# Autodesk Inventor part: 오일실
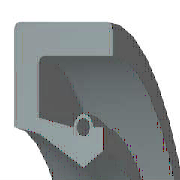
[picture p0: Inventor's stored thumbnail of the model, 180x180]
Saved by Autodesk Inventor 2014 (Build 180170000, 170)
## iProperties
IsCustomPart: 0
Created: 2009-02
Part Number: 오일실
Material: 고무
Description: 오일-실
Document SubType Name: Modeling
Standard: KS B 2804
Designer: 한국산업디자인학원 [http://gmhk.co.kr]
Standards Organization: KS
Language: ko-KR
Size Designation: S - 17 30 8
Categories: <MemberInstance><Categories><Category DisplayName="샤프트 부품" InternalName="7f7aeb1f-a693-4053-b835-cee3144e0d98" Mnemonic="SHFT"><Category DisplayName="실링" Intern
Density: 0.93 g/cm^3
Mass: 1.6913 g
Surface Area: 28.0102 cm^2
Volume: 1.81861 cm^3
Appearance: 고무 - 검은색 - 버전 1.1
Author: pww
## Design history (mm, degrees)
revolve "본체" stored, may be unused: angle "d17" = 90 deg
revolve "스프링1" stored, may be unused: angle "d18" = 90 deg
body "Solid1"
sketch "스케치1"
  geometry: L1 (0, 15)-(8, 15); L2 (8, 15)-(8, 13.75); L3 (8, 13.75)-(1.75, 13.75); L4 (0, 15)-(0, 10.6); L5 (0, 10.6)-(1.75, 10.25); L6 (1.75, 10.25)-(4.9, 8.5); L7 (4.9, 8.5)-(0, 8.5); L8 (6.3, 9.375)-(6.3, 10.6); L9 (0, 0)-(9.586, 0) reference; L10 (4.9, 8.5)-(6.3, 9.375); L11 (0, 18)-(0, -3) reference; L12 (-1.917, 0)-(11.503, 0) reference; L13 (4.2, 10.6)-(1.75, 11.09); L14 (1.75, 11.09)-(1.75, 13.75); L15 (6.3, 10.6)-(5.6, 10.6); C1 r 0.455 at (4.9, 10.6); A1 r 0.7 centre (4.9, 10.6) between (5.6, 10.6) and (4.2, 10.6)
  constraints: 26 end point, 5 horizontal alignment, 4 perpendicular, 2 centre point, 2 collinear, 2 horizontal, 2 parallel, 2 point on circle, 2 point on line, 2 vertical alignment, 1 coincident
  dimensions: "d0" = 30 diameter of L1 L9 (= SD2); "d1" = 18.75 diameter of L8.start L9 (= ABDM); "d2" = 1.25 distance of L1.end L2.end (computed from SD); "d3" = 0.91 diameter of C1 (= SPDI); "d4" = 1.4 diameter of A1 (= SPDA); "d5" = 17 diameter of L6.end L9 (= NND); "d6" = 20.5 diameter of L5.end L9 (= TKDM); "d7" = 21.2 diameter of L4.end L9 (= HLDM); "d8" = 4.9 distance from line of C1.centre L4 (= SPDST); "d9" = 6.3 distance between parallel lines of L8 L4 (= SDI); "d10" = 8 distance between parallel lines of L2 L4 (= SWDT); "d12" = 1.75 distance between parallel lines of L14 L4 (= SD)
fillet "모깎기1" dims "d11" = 0.3 (= RR)
other parameters: "SD2" = 30 [user parameter; used in 1 equation term], "SWDT" = 8 [user parameter; used in 1 equation term], "RR" = 0.3 [user parameter; used in 1 equation term], "SD" = 1.75 [user parameter; used in 2 equation terms], "NND" = 17 [user parameter; used in 1 equation term], "SPDA" = 1.4 [user parameter; used in 1 equation term], "SPDI" = 0.91 [user parameter; used in 1 equation term], "TKDM" = 20.5 [user parameter; used in 1 equation term], "HLDM" = 21.2 [user parameter; used in 1 equation term], "ABDM" = 18.75 [user parameter; used in 1 equation term], "SDI" = 6.3 [user parameter; used in 1 equation term], "SPDST" = 4.9 [user parameter; used in 1 equation term], "d13" = 0, "d14" = 0, "d15" = 0, "LAB" = 0.35 [user parameter]
